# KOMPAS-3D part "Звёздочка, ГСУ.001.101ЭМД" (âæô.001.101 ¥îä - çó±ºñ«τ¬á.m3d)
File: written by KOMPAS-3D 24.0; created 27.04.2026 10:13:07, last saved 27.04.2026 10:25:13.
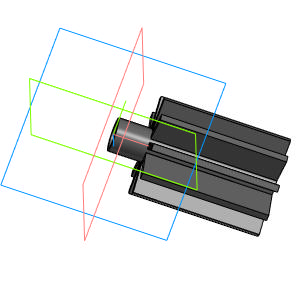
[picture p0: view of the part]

Document properties: Автор: USG_411; Полное имя файла: C:\Users\USG_411\Desktop\ГМ2704_411-15\ГСУ.001.101 ЭМД - Звёздочка.m3d

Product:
- Part/product: Звёздочка  | designation ГСУ.001.101ЭМД
    Масса: 0.070568

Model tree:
1. Эскиз:1
2. Элемент выдавливания:1
     Расстояние 1 = 48
3. Эскиз:2  (with: Грань.Элемент выдавливания:1, Ребро.Элемент выдавливания:1)
4. Элемент выдавливания:2
     Расстояние 2 = 38
5. Массив по концентрической сетке:1  (with: Элемент выдавливания:2, Эскиз:2, Грань.Элемент выдавливания:1)  (10 pattern instances)
     Шаг 2 = 360

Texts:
  ГСУ.001.101
  ГСУ.001.101 ЭМД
